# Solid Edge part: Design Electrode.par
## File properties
Author: Dave
Template: Normal 2.par
Last saved by: Dave
Revision: 4
Application: Solid Edge
Accuracy: 0.990
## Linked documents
DKW001-01.027Squared Leg Foot.par
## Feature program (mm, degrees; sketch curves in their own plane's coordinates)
part copy "CopiedPart_3"  YScale = 1.008; ZScale = 1.008
Other named dimensions: "Offset_2": Distance = 0.075 mm
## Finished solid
Body 1: solid body, 252 faces, 528 edges, 282 vertices.
  Faces by surface: cylinder 102, offset 48, plane 43, sphere 38, torus 16, cone 5
  Edges by curve: line 200, curve on surface 172, circle 156
Bounding box of the edges (mm; curved faces can reach further): 61.840 x 61.840 x 40.470, from (-26.5143, -35.3253, -5.115) to (35.3253, 26.5143, 35.355).
Cylindrical faces by radius (mm): R0.429 x48, R0.579 x48, R1.083 x4, R4.1485 x1, R7.3225 x1
Conical faces (half-angle, radius in mm at the cone's reference point): 1 deg R7.131 x1, 1 deg R20.337 x1, 1 deg R23.511 x3
Toroidal faces (ring radius, tube radius in mm): R0.504 r0.579 x3, R1.512 r0.429 x1, R6.1209 r0.579 x1, R6.7435 r0.579 x1, R7.5513 r0.429 x1, R7.7515 r0.429 x1, R19.9167 r0.429 x1, R21.1184 r0.579 x1, R22.7296 r0.579 x3, R23.9313 r0.429 x3
Spherical faces by radius (mm): R0.429 x26, R0.579 x12
Planar faces by outward normal: +x 2, +y 1, +z 3, -x 1, -y 2, -z 7, oblique 27
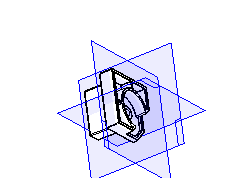
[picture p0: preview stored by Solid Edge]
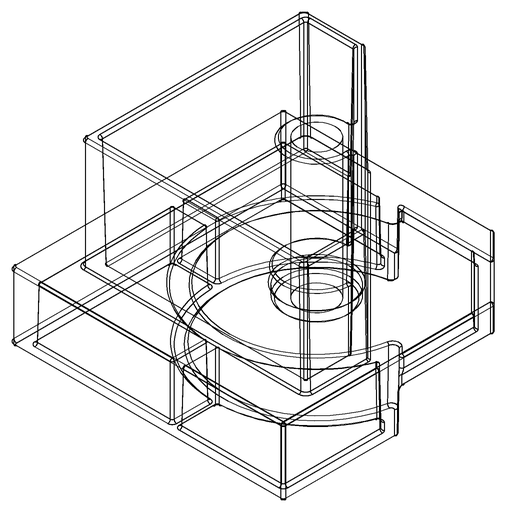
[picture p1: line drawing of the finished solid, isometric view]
